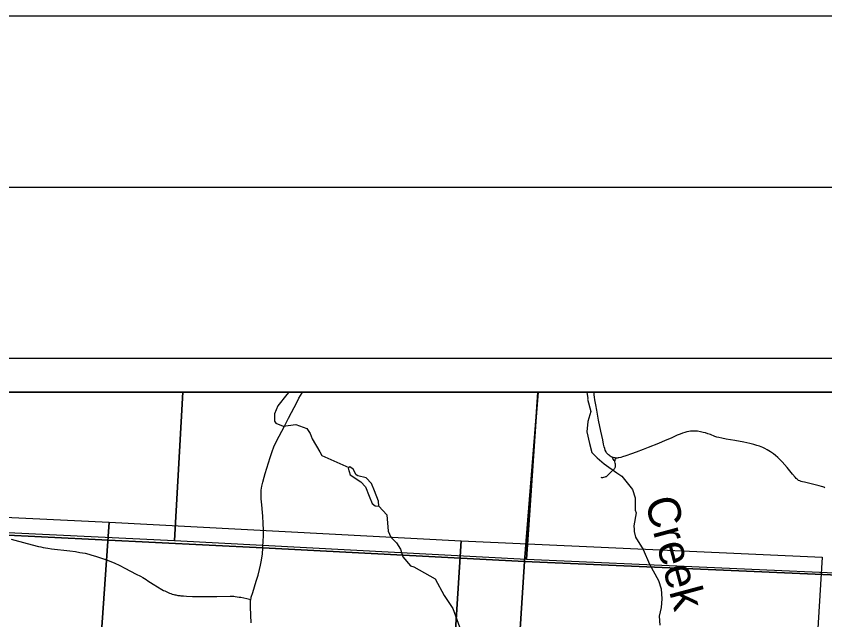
# Model space of a CAD drawing. Extents: x 0 to 34, y 0 to 22.
# Drawn here: x 27.118 to 29.485, y 20.235 to 22 of the extents above; entities that cross this region are included whole.
import ezdxf

# ---------------------------------------------------------------- set-up
doc = ezdxf.new("R2010")
doc.units = 0
for name, color, linetype in [('GM_X_County_Road', 7, 'Continuous'), ('GM_X_County_Text', 7, 'Continuous'), ('GM_X_Minor_River', 7, 'Continuous'), ('GM_X_Minor_River_Text', 7, 'Continuous'), ('GM_X_Section', 7, 'Continuous'), ('GM_X_State_Route', 7, 'Continuous'), ('GM_X_State_Shield', 7, 'Continuous'), ('GM_X_Township_Road', 7, 'Continuous'), ('SH_Border', 7, 'Continuous'), ('SH_Cut_Line', 7, 'Continuous'), ('SH_Data', 7, 'Continuous')]:
    doc.layers.add(name, color=color, linetype=linetype)

msp = doc.modelspace()

# ---------------------------------------------------------------- linework, layer by layer
at = {"layer": 'GM_X_County_Road'}
msp.add_lwpolyline([(29.4856, 20.6206), (29.4824, 20.6222), (29.479, 20.6235), (29.4753, 20.6248), (29.4689, 20.6266), (29.4572, 20.6296), (29.4488, 20.6316), (29.4257, 20.6367), (29.4198, 20.6381), (29.4157, 20.6393), (29.4122, 20.6407), (29.4086, 20.6425), (29.4059, 20.6442), (29.4039, 20.6459), (29.4017, 20.6477), (29.398, 20.6517), (29.3906, 20.6607), (29.3751, 20.6797), (29.3605, 20.6965), (29.3528, 20.7046), (29.3474, 20.7098), (29.3412, 20.7151), (29.3353, 20.7196), (29.326, 20.726), (29.3167, 20.7318), (29.3098, 20.7357), (29.3041, 20.7386), (29.2989, 20.7408), (29.2939, 20.7426), (29.2862, 20.7449), (29.2772, 20.7473), (29.2656, 20.7501), (29.248, 20.7538), (29.2215, 20.759), (29.1961, 20.7634), (29.1839, 20.7655), (29.1755, 20.7674), (29.1695, 20.769), (29.1631, 20.7712), (29.1502, 20.7761), (29.143, 20.7787), (29.1359, 20.7811), (29.1291, 20.7829), (29.1211, 20.7848), (29.1125, 20.7861), (29.1073, 20.7865), (29.1019, 20.7867), (29.0972, 20.7866), (29.0922, 20.7862), (29.0871, 20.7855), (29.0814, 20.7843), (29.0754, 20.7827), (29.0691, 20.7805), (29.062, 20.7778), (29.0534, 20.7744), (29.0355, 20.7663), (29.0183, 20.7588), (28.9981, 20.7504), (28.9681, 20.7383), (28.954, 20.7326), (28.9326, 20.7249), (28.9198, 20.7204), (28.9028, 20.7146), (28.8928, 20.7112), (28.8881, 20.7098), (28.8827, 20.7085), (28.8804, 20.708), (28.8774, 20.7077), (28.8744, 20.7077), (28.8717, 20.7079), (28.8692, 20.7082), (28.8659, 20.709), (28.8642, 20.7095), (28.8627, 20.7101), (28.8601, 20.7113), (28.8574, 20.7129), (28.8547, 20.7148), (28.8522, 20.7167), (28.85, 20.7189), (28.8482, 20.7209), (28.8467, 20.7228), (28.8448, 20.7259), (28.8427, 20.7303), (28.8409, 20.7355), (28.8395, 20.7409), (28.8378, 20.7481), (28.8351, 20.7608), (28.8296, 20.7868), (28.823, 20.8182), (28.8175, 20.8482), (28.8149, 20.8635), (28.8125, 20.8782), (28.8114, 20.8859), (28.8105, 20.8924), (28.8101, 20.8975), (28.81, 20.9)], dxfattribs=at)
at = {"layer": 'GM_X_County_Text'}
for points in [[(28.6466, 20.9), (23.8372, 20.9), (23.8372, 20.6485), (24.4417, 20.6174), (26.0533, 20.5337), (26.781, 20.4973), (27.0539, 20.4845), (27.8401, 20.4449), (28.6062, 20.4055)], [(30.6372, 20.3098), (30.6372, 20.9), (28.6466, 20.9), (28.6062, 20.4055), (29.547, 20.3639)]]:
    msp.add_lwpolyline(points, close=True, dxfattribs=at)
for points in [[(28.4159, 17.3358), (28.4427, 17.7695), (28.4677, 18.1732), (28.5249, 19.1245), (28.5443, 19.4375), (28.5808, 20.0106), (28.6062, 20.4055), (27.8401, 20.4449), (27.0539, 20.4845), (26.781, 20.4973), (26.0533, 20.5337), (24.4417, 20.6174), (23.8372, 20.6485), (23.8372, 14.4177)], [(29.547, 20.3639), (28.6062, 20.4055), (28.5808, 20.0106), (28.5443, 19.4375), (28.5249, 19.1245), (28.4677, 18.1732), (28.4427, 17.7695), (28.4159, 17.3358)]]:
    msp.add_lwpolyline(points, dxfattribs=at)
at = {"layer": 'GM_X_Minor_River'}
for points in [[(27.9162, 20.9), (27.9103, 20.894), (27.8844, 20.8607), (27.8742, 20.8371), (27.8741, 20.8321), (27.8747, 20.8158), (27.8787, 20.81), (27.8996, 20.8013), (27.9371, 20.8058), (27.9693, 20.7945), (27.9791, 20.7798), (27.9843, 20.7637), (28.0073, 20.7261), (28.013, 20.7149), (28.0925, 20.6796)], [(28.7884, 20.9), (28.7912, 20.882), (28.7908, 20.8801), (28.7999, 20.8437), (28.7916, 20.8144), (28.789, 20.7843), (28.7962, 20.7498), (28.803, 20.7239), (28.8193, 20.7088), (28.839, 20.6909), (28.8764, 20.6648), (28.8916, 20.6546), (28.9219, 20.6159), (28.9302, 20.5916), (28.9299, 20.5551), (28.9329, 20.5471), (28.9265, 20.5091), (28.9273, 20.4988), (28.9276, 20.4931), (28.9307, 20.4764), (28.9538, 20.44), (28.9723, 20.3978), (28.9981, 20.35), (29.0064, 20.3257), (29.008, 20.2957), (29.0065, 20.2706), (29.0008, 20.2451), (29.002, 20.2189)], [(28.0964, 20.6587), (28.1268, 20.6384), (28.141, 20.6231), (28.1519, 20.5962), (28.16, 20.5743), (28.1692, 20.5683), (28.1794, 20.5668), (28.1791, 20.5812), (28.1668, 20.6116), (28.1584, 20.6336), (28.143, 20.65), (28.1182, 20.6553), (28.1134, 20.6589), (28.1044, 20.6751), (28.0952, 20.6819), (28.0905, 20.6779), (28.0964, 20.6587)], [(28.1794, 20.5668), (28.2032, 20.5421), (28.2074, 20.4941), (28.2152, 20.4768), (28.2317, 20.4599), (28.2432, 20.441), (28.2505, 20.4187), (28.2724, 20.3926), (28.2827, 20.3892)], [(28.2827, 20.3892), (28.3446, 20.3542), (28.3707, 20.3061), (28.396, 20.2679), (28.4161, 20.2145), (28.4264, 20.1435), (28.4326, 20.1177), (28.4403, 20.1015)]]:
    msp.add_lwpolyline(points, dxfattribs=at)
at = {"layer": 'GM_X_Section'}
for points in [[(26.3334, 20.5711), (27.3906, 20.5203), (27.3196, 19.501), (26.2655, 19.5533)], [(27.3906, 20.5203), (28.4213, 20.4653), (28.356, 19.4486), (27.3196, 19.501)], [(28.4213, 20.4653), (29.477, 20.4182), (29.4164, 19.4097), (28.356, 19.4486)]]:
    msp.add_lwpolyline(points, close=True, dxfattribs=at)
at = {"layer": 'GM_X_State_Route'}
for points in [[(27.8403, 20.4443), (27.8406, 20.4477), (27.8414, 20.4646), (27.8422, 20.4801), (27.8423, 20.4982), (27.8418, 20.5162), (27.8406, 20.5373), (27.8397, 20.548), (27.8371, 20.5704), (27.8356, 20.5882), (27.8352, 20.5979), (27.8353, 20.6062), (27.8359, 20.614), (27.8366, 20.6198), (27.8377, 20.6257), (27.8401, 20.6368), (27.8441, 20.6522), (27.8471, 20.6626), (27.8614, 20.7093), (27.8674, 20.7269), (27.8727, 20.7402), (27.8794, 20.7548), (27.9046, 20.8033), (27.9153, 20.8243), (27.9406, 20.8721), (27.9462, 20.8827), (27.955, 20.8989), (27.9555, 20.9)], [(27.1033, 20.4709), (27.1506, 20.4579), (27.1838, 20.4491), (27.1906, 20.4476), (27.1976, 20.4461), (27.2045, 20.4449), (27.2114, 20.4437), (27.2216, 20.4424), (27.2758, 20.436), (27.2918, 20.434), (27.3052, 20.4319), (27.3201, 20.4291), (27.3307, 20.4266), (27.3403, 20.4238), (27.3503, 20.4207), (27.3626, 20.4167), (27.3739, 20.4128), (27.3858, 20.4087), (27.397, 20.4043), (27.4056, 20.4009), (27.4112, 20.3985), (27.4162, 20.3961), (27.4215, 20.3936), (27.436, 20.3859), (27.4696, 20.3682), (27.482, 20.3619), (27.4888, 20.3584), (27.494, 20.3554), (27.4988, 20.3524), (27.5041, 20.349), (27.5198, 20.3387), (27.5447, 20.3236), (27.55, 20.3206), (27.5532, 20.3189), (27.557, 20.317), (27.5613, 20.3151), (27.5674, 20.3127), (27.5714, 20.3112), (27.5754, 20.31), (27.5795, 20.3088), (27.5832, 20.3079), (27.5861, 20.3072), (27.5887, 20.3067), (27.5915, 20.3062), (27.5943, 20.3057), (27.5979, 20.3053), (27.6005, 20.305), (27.6082, 20.3045), (27.6169, 20.304), (27.6346, 20.3031), (27.6561, 20.3028), (27.7056, 20.3025), (27.7447, 20.3037), (27.7483, 20.3036), (27.752, 20.3036), (27.7558, 20.3033), (27.7594, 20.303), (27.7656, 20.3022), (27.771, 20.3013), (27.7759, 20.3004), (27.7939, 20.2968), (27.8051, 20.2945)], [(27.8051, 20.2945), (27.8058, 20.2975), (27.8066, 20.3005), (27.8108, 20.3142), (27.8213, 20.3474), (27.8267, 20.3654), (27.8308, 20.3815), (27.8339, 20.3943), (27.8359, 20.4043), (27.8377, 20.4152), (27.8389, 20.4271), (27.8403, 20.4443)], [(27.8059, 20.2262), (27.8051, 20.2485), (27.8045, 20.2725), (27.8045, 20.286), (27.8047, 20.291), (27.8051, 20.2945)]]:
    msp.add_lwpolyline(points, dxfattribs=at)
at = {"layer": 'GM_X_State_Shield'}
for points in [[(27.6063, 20.9), (26.5463, 20.9), (26.5242, 20.5177), (27.5814, 20.4669)], [(28.6454, 20.9), (27.6063, 20.9), (27.5814, 20.4669), (28.6121, 20.4119)], [(29.7008, 20.9), (28.6454, 20.9), (28.6121, 20.4119), (29.6678, 20.3647), (29.6833, 20.6236), (29.6992, 20.8762)]]:
    msp.add_lwpolyline(points, close=True, dxfattribs=at)
at = {"layer": 'GM_X_Township_Road'}
for points in [[(28.8297, 20.6517), (28.8314, 20.6513), (28.8332, 20.6511), (28.8351, 20.6513), (28.8387, 20.6519), (28.8421, 20.6527), (28.8441, 20.6534), (28.8458, 20.6541), (28.8473, 20.6552), (28.8485, 20.6561), (28.8521, 20.6595), (28.8579, 20.665), (28.8684, 20.6751), (28.87, 20.6769), (28.8711, 20.6786), (28.8719, 20.6802), (28.8723, 20.682), (28.8726, 20.6838), (28.8728, 20.6857), (28.8727, 20.688), (28.8724, 20.6901), (28.8719, 20.6925), (28.871, 20.6964), (28.8708, 20.6982), (28.8712, 20.7006), (28.8718, 20.7026), (28.8728, 20.7048), (28.8744, 20.7077)], [(28.8708, 20.6982), (28.8688, 20.7004), (28.8668, 20.7031), (28.8647, 20.7061), (28.8627, 20.7101)]]:
    msp.add_lwpolyline(points, dxfattribs=at)
at = {"layer": 'SH_Border'}
msp.add_lwpolyline([(1.5, 21.5), (33.5, 21.5), (33.5, 0.5), (1.5, 0.5)], close=True, dxfattribs=at)
at = {"layer": 'SH_Cut_Line'}
msp.add_lwpolyline([(0, 0), (34, 0), (34, 22), (0, 22)], close=True, dxfattribs=at)
msp.add_lwpolyline([(30.6372, 20.9), (23.8372, 20.9), (23.8372, 14.4177)], dxfattribs=at)
at = {"layer": 'SH_Data'}
for points in [[(23.7372, 21), (30.7372, 21), (30.7372, 14), (23.7372, 14)], [(23.8372, 20.9), (30.6372, 20.9), (30.6372, 14.1), (23.8372, 14.1)]]:
    msp.add_lwpolyline(points, close=True, dxfattribs=at)

# ---------------------------------------------------------------- texts
at = {"layer": 'GM_X_Minor_River_Text'}
msp.add_text('Creek', height=0.0947, rotation=285.0007, dxfattribs=at).set_placement((28.9581, 20.5827))

doc.saveas('drawing.dxf')
